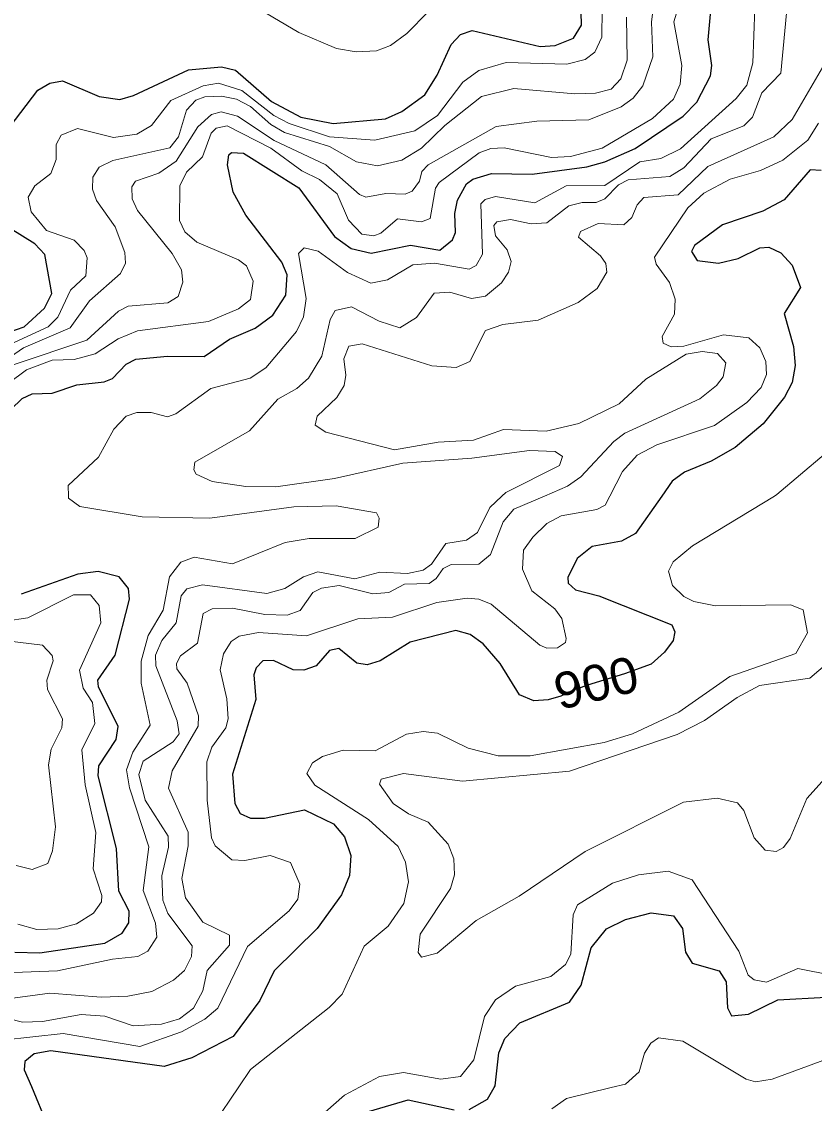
# Model space of a CAD drawing. Extents: x 473.9 to 500, y 7733.1 to 7760.8.
# Drawn here: x 484.023 to 485.784, y 7735.72 to 7738.123 of the extents above; entities that cross this region are included whole.
import ezdxf
from ezdxf.enums import TextEntityAlignment as Align

# ---------------------------------------------------------------- set-up
doc = ezdxf.new("R2010")
doc.units = 0
doc.header["$LTSCALE"] = 0.032
doc.layers.add('1', color=7, linetype='Continuous', lineweight=25)
doc.layers.add('2', color=7, linetype='Continuous', lineweight=13)
doc.layers.add('61', color=7, linetype='Continuous')

msp = doc.modelspace()

# ---------------------------------------------------------------- linework, layer by layer
at = {"layer": '1'}
for points in [[(484.9192, 7737.9607), (484.9465, 7738.0038), (484.977, 7738.0723), (484.9983, 7738.0943), (485.0241, 7738.103), (485.1747, 7738.0679), (485.2086, 7738.0698), (485.2494, 7738.086), (485.267, 7738.1149), (485.2622, 7738.2885)], [(485.5531, 7738.0026), (485.5561, 7738.0253), (485.5483, 7738.0828), (485.5549, 7738.156)], [(483.9336, 7737.8065), (484.0593, 7737.9707), (484.086, 7737.9864), (484.1142, 7737.9914), (484.1956, 7737.9567), (484.2415, 7737.9498), (484.272, 7737.9587), (484.3942, 7738.0157), (484.4673, 7738.0227), (484.498, 7738.0154), (484.5781, 7737.9452), (484.6435, 7737.9109), (484.7154, 7737.8966), (484.8316, 7737.9072), (484.8679, 7737.9232), (484.9192, 7737.9607)], [(483.9989, 7737.2616), (484.0248, 7737.2856), (484.0465, 7737.2963), (484.091, 7737.2979), (484.1456, 7737.3163), (484.2067, 7737.323), (484.2248, 7737.3306), (484.2555, 7737.3618), (484.2772, 7737.3734), (484.3473, 7737.3803), (484.429, 7737.3789), (484.4848, 7737.4178), (484.5421, 7737.4419), (484.581, 7737.4713), (484.6101, 7737.5151), (484.6129, 7737.5605), (484.6011, 7737.5886), (484.5216, 7737.6932), (484.4928, 7737.7442), (484.4806, 7737.8052), (484.4836, 7737.8274), (484.4893, 7737.8321), (484.516, 7737.8306), (484.6391, 7737.7538), (484.7184, 7737.646), (484.755, 7737.6187), (484.7994, 7737.6088), (484.887, 7737.6263), (484.9519, 7737.6152), (484.9806, 7737.6382), (484.9871, 7737.6543), (484.9855, 7737.6971), (484.9912, 7737.7265), (485.0116, 7737.7625), (485.0257, 7737.7727), (485.0668, 7737.7855), (485.1575, 7737.7841), (485.2784, 7737.8007), (485.319, 7737.8118), (485.3859, 7737.8413), (485.4924, 7737.913), (485.5233, 7737.9441), (485.5531, 7738.0026)], [(485.7991, 7737.792), (485.7746, 7737.7937), (485.7168, 7737.7274), (485.6694, 7737.7023), (485.5804, 7737.6714), (485.5181, 7737.6254), (485.5113, 7737.6126), (485.524, 7737.5925), (485.5714, 7737.5863), (485.6149, 7737.5967), (485.6628, 7737.6203), (485.6831, 7737.622), (485.7095, 7737.6098), (485.7347, 7737.5822), (485.7532, 7737.5328), (485.7173, 7737.4747), (485.738, 7737.4015), (485.7413, 7737.3595)], [(483.9092, 7737.4033), (484.0291, 7737.445), (484.0737, 7737.4866), (484.0902, 7737.5189), (484.0747, 7737.6057), (484.0524, 7737.6296), (483.9482, 7737.6939)], [(485.7413, 7737.3595), (485.7347, 7737.3218), (485.7175, 7737.289), (485.6701, 7737.2297), (485.6085, 7737.177), (485.5549, 7737.1465), (485.4953, 7737.1223), (485.4679, 7737.1022), (485.445, 7737.0693), (485.3868, 7736.9858), (485.3559, 7736.969), (485.2902, 7736.9569), (485.2572, 7736.9302), (485.2365, 7736.8881), (485.2375, 7736.8758), (485.2535, 7736.8606), (485.3054, 7736.8473), (485.4672, 7736.7833), (485.4742, 7736.7677), (485.4701, 7736.7486), (485.4513, 7736.7222), (485.4216, 7736.6959), (485.3623, 7736.6742), (485.29, 7736.6524), (485.2481, 7736.6381), (485.2207, 7736.6247), (485.193, 7736.6166), (485.161, 7736.6141), (485.1288, 7736.6277), (485.0863, 7736.6973), (485.0486, 7736.7407), (485.0194, 7736.7615), (484.9876, 7736.7708), (484.8863, 7736.7446), (484.8193, 7736.7032), (484.7911, 7736.6943), (484.7677, 7736.6979), (484.7275, 7736.7307), (484.7073, 7736.7265), (484.6774, 7736.6923), (484.65, 7736.6823), (484.6266, 7736.683), (484.583, 7736.7039), (484.5588, 7736.703), (484.5444, 7736.6876), (484.5391, 7736.6719), (484.5432, 7736.6171), (484.4913, 7736.4514), (484.497, 7736.3862), (484.5083, 7736.364), (484.5319, 7736.3537), (484.5625, 7736.3537), (484.6519, 7736.3721), (484.7158, 7736.3412), (484.7406, 7736.3127), (484.7545, 7736.2706), (484.7514, 7736.2266), (484.7337, 7736.1832), (484.68, 7736.1091), (484.5842, 7736.0149), (484.552, 7735.9489), (484.4932, 7735.8689), (484.4011, 7735.8212), (484.34, 7735.8022), (484.0878, 7735.8374), (484.0509, 7735.8306), (484.03, 7735.8137), (484.029, 7735.795), (484.0448, 7735.7575), (484.0801, 7735.6735)], [(484.008, 7736.0563), (484.0637, 7736.0547), (484.2081, 7736.0761), (484.2467, 7736.0982), (484.2617, 7736.1215), (484.2618, 7736.1472), (484.239, 7736.1914), (484.2343, 7736.2867), (484.1935, 7736.4476), (484.1946, 7736.4702), (484.2333, 7736.5283), (484.2376, 7736.5573), (484.1938, 7736.6453), (484.1927, 7736.6601), (484.2312, 7736.7155), (484.263, 7736.8405), (484.2605, 7736.8642), (484.24, 7736.8898), (484.1932, 7736.9019), (484.1482, 7736.8957), (484.0222, 7736.8514)], [(485.0172, 7735.7065), (485.0579, 7735.73), (485.0729, 7735.7559), (485.0751, 7735.7597), (485.0829, 7735.8325), (485.0964, 7735.8648), (485.1299, 7735.8994), (485.2399, 7735.9449), (485.2662, 7735.9828), (485.2881, 7736.0661), (485.3222, 7736.1079), (485.3645, 7736.1291), (485.4213, 7736.1438), (485.471, 7736.1372)], [(485.471, 7736.1372), (485.4914, 7736.1087), (485.4977, 7736.0564), (485.5127, 7736.0317), (485.573, 7736.0144), (485.5885, 7735.9905), (485.5913, 7735.9328), (485.6, 7735.9147), (485.638, 7735.9182), (485.703, 7735.9505), (485.81, 7735.9561)], [(484.7815, 7735.6983), (484.8822, 7735.7282), (484.9839, 7735.7057)]]:
    msp.add_lwpolyline(points, dxfattribs=at)
at = {"layer": '2'}
for points in [[(485.0358, 7736.9886), (485.063, 7737.044), (485.0901, 7737.0693), (485.0988, 7737.0774), (485.2177, 7737.1369), (485.2248, 7737.1568), (485.2084, 7737.1681), (485.151, 7737.1704), (485.0229, 7737.1535), (484.8697, 7737.1424), (484.7184, 7737.1083), (484.5876, 7737.0894), (484.5213, 7737.0902), (484.4467, 7737.1015), (484.4111, 7737.1177), (484.4058, 7737.1273), (484.4083, 7737.1444), (484.5291, 7737.2144), (484.5925, 7737.2846), (484.6346, 7737.3082), (484.6602, 7737.3309), (484.6903, 7737.3797), (484.7084, 7737.4611), (484.72, 7737.4817), (484.7556, 7737.4895), (484.8173, 7737.4574), (484.8633, 7737.4432), (484.9002, 7737.4656), (484.9394, 7737.5196), (484.9741, 7737.5219), (485.0224, 7737.5083), (485.0535, 7737.5134), (485.089, 7737.5431), (485.1045, 7737.5662), (485.1105, 7737.5902), (485.1021, 7737.6159), (485.0756, 7737.6469), (485.0723, 7737.6698), (485.0786, 7737.678), (485.1092, 7737.6836), (485.1554, 7737.674), (485.1902, 7737.676), (485.2385, 7737.7135), (485.2685, 7737.7213), (485.2991, 7737.721), (485.3189, 7737.7296), (485.3489, 7737.7603), (485.3708, 7737.7719), (485.463, 7737.7793), (485.4943, 7737.7985), (485.5552, 7737.863), (485.6271, 7737.8915), (485.6468, 7737.9104), (485.6674, 7737.9646), (485.7095, 7738.0083), (485.7274, 7738.1971)], [(484.9268, 7738.1455), (484.879, 7738.0965), (484.8425, 7738.0697), (484.8118, 7738.0578), (484.7663, 7738.0557), (484.7228, 7738.0633), (484.6391, 7738.0988), (484.4493, 7738.2114)], [(484.8214, 7737.6532), (484.8583, 7737.6847), (484.9114, 7737.678), (484.9308, 7737.6857), (484.9424, 7737.7528), (484.9509, 7737.7654), (485.0398, 7737.8315), (485.0653, 7737.8409), (485.0954, 7737.8427), (485.1999, 7737.8211), (485.2426, 7737.8231), (485.313, 7737.8417), (485.4245, 7737.9078), (485.4711, 7737.9511), (485.4863, 7737.9843), (485.4896, 7738.0255), (485.4719, 7738.1228), (485.4904, 7738.1831)], [(483.9509, 7737.385), (484.0823, 7737.4451), (484.1034, 7737.4667), (484.1319, 7737.5264), (484.166, 7737.5586), (484.1685, 7737.5983), (484.1624, 7737.6149), (484.1402, 7737.6376), (484.0783, 7737.6587), (484.0443, 7737.7008), (484.0375, 7737.7331), (484.0524, 7737.7585), (484.088, 7737.7857), (484.0998, 7737.817), (484.1, 7737.8497), (484.1112, 7737.8706), (484.1471, 7737.8854), (484.2276, 7737.8659), (484.2794, 7737.8728), (484.3114, 7737.8919), (484.3544, 7737.9478), (484.4263, 7737.9804), (484.4607, 7737.9859), (484.5121, 7737.97), (484.5831, 7737.9146), (484.6178, 7737.897), (484.7073, 7737.867), (484.808, 7737.8597), (484.8969, 7737.8807), (484.9471, 7737.9147), (485.003, 7737.9888), (485.0385, 7738.0146), (485.0996, 7738.0323), (485.2341, 7738.0282), (485.2752, 7738.0392), (485.2961, 7738.0551), (485.3117, 7738.0882), (485.3129, 7738.1509)], [(485.4284, 7738.1717), (485.4221, 7738.1215), (485.4252, 7738.045), (485.403, 7737.98), (485.3813, 7737.9532), (485.3551, 7737.9335), (485.2829, 7737.9047), (485.1677, 7737.9022), (485.0772, 7737.8901), (484.926, 7737.8048), (484.912, 7737.7904), (484.9073, 7737.7684), (484.8909, 7737.7466), (484.8753, 7737.7399), (484.832, 7737.7414), (484.788, 7737.7334), (484.7736, 7737.7387), (484.6989, 7737.8048), (484.5845, 7737.8592), (484.5028, 7737.9128), (484.4661, 7737.9223), (484.4452, 7737.9166), (484.4143, 7737.8896), (484.3668, 7737.8129), (484.3277, 7737.7865), (484.2764, 7737.7687), (484.2678, 7737.756), (484.269, 7737.7292), (484.2809, 7737.7034), (484.3579, 7737.6078), (484.3781, 7737.5715), (484.3815, 7737.5446), (484.3711, 7737.5124), (484.3481, 7737.4985), (484.2597, 7737.491), (484.2386, 7737.4796), (484.1683, 7737.4156), (484.0067, 7737.3614)], [(485.6518, 7738.1525), (485.6472, 7738.0314), (485.6339, 7737.9821), (485.6101, 7737.9521), (485.4864, 7737.8402), (485.4432, 7737.8187), (485.3966, 7737.8118), (485.3186, 7737.7588), (485.2331, 7737.7583), (485.1629, 7737.7207), (485.0761, 7737.7349), (485.0528, 7737.7277), (485.0435, 7737.7182), (485.0473, 7737.6066), (485.0329, 7737.5815), (485.0175, 7737.5734), (484.9404, 7737.5862), (484.8922, 7737.583), (484.8362, 7737.5492), (484.7991, 7737.5421)], [(483.8919, 7737.3051), (484.0273, 7737.3981), (484.1311, 7737.4428), (484.1739, 7737.5031), (484.2431, 7737.5632), (484.2536, 7737.5865), (484.2527, 7737.6101), (484.2307, 7737.667), (484.1893, 7737.726), (484.1808, 7737.7505), (484.1816, 7737.7773), (484.1953, 7737.7994), (484.2258, 7737.8148), (484.3524, 7737.8423), (484.3717, 7737.8672), (484.3893, 7737.9265), (484.4102, 7737.9482), (484.43, 7737.9562), (484.4671, 7737.9577), (484.5003, 7737.951), (484.5319, 7737.9343), (484.5767, 7737.8946), (484.6073, 7737.8765), (484.707, 7737.8458), (484.7669, 7737.8118), (484.8139, 7737.8025), (484.8676, 7737.8154), (484.9117, 7737.8416), (484.963, 7737.8925), (485.0445, 7737.9567), (485.1164, 7737.9745), (485.2517, 7737.9626), (485.2981, 7737.9642), (485.333, 7737.973), (485.3539, 7737.996), (485.3681, 7738.0373), (485.3666, 7738.1328)], [(485.8024, 7738.0211), (485.7351, 7737.9059), (485.694, 7737.8674), (485.5476, 7737.8014), (485.4814, 7737.7379), (485.4051, 7737.7326), (485.3904, 7737.7159), (485.379, 7737.6879), (485.361, 7737.6717), (485.304, 7737.6746), (485.2648, 7737.6571), (485.2604, 7737.6443), (485.3092, 7737.6031), (485.3207, 7737.5854), (485.3232, 7737.5664), (485.3014, 7737.53), (485.2598, 7737.4993), (485.1709, 7737.4602), (485.092, 7737.4501), (485.0534, 7737.4366), (485.0191, 7737.3678), (484.9881, 7737.3547), (484.9346, 7737.3582), (484.7795, 7737.4076), (484.7501, 7737.402), (484.7387, 7737.3743), (484.7433, 7737.338), (484.7395, 7737.3146), (484.7233, 7737.288), (484.6794, 7737.2467), (484.6754, 7737.227), (484.6993, 7737.2108), (484.8516, 7737.1717), (484.9485, 7737.189), (485.0273, 7737.1934), (485.0937, 7737.2172), (485.188, 7737.2132), (485.261, 7737.2303), (485.3504, 7737.2743), (485.4099, 7737.3289), (485.4995, 7737.3842), (485.5348, 7737.3901), (485.5692, 7737.3858), (485.5875, 7737.365), (485.5817, 7737.334), (485.5668, 7737.3145), (485.5299, 7737.2854), (485.3634, 7737.2091), (485.3385, 7737.1906), (485.2653, 7737.1119)], [(483.9805, 7735.8609), (484.1156, 7735.8754), (484.286, 7735.8464), (484.3785, 7735.8794), (484.4299, 7735.9075), (484.4589, 7735.9316), (484.5248, 7736.0691), (484.6173, 7736.1479), (484.6366, 7736.1737), (484.6414, 7736.2074), (484.6205, 7736.2557), (484.5755, 7736.2709), (484.5192, 7736.2597), (484.4902, 7736.2613), (484.4532, 7736.2926), (484.4452, 7736.3103), (484.4355, 7736.394), (484.4347, 7736.4792), (484.446, 7736.5113), (484.4766, 7736.5548), (484.4822, 7736.5741), (484.479, 7736.6191), (484.4645, 7736.6834), (484.4717, 7736.7188), (484.4886, 7736.7461), (484.5063, 7736.7582), (484.5497, 7736.7662), (484.6559, 7736.759), (484.77, 7736.7968), (484.8472, 7736.8), (484.9453, 7736.8329), (485.0128, 7736.8426), (485.0386, 7736.8402), (485.0659, 7736.8289), (485.1744, 7736.7381), (485.1897, 7736.7316), (485.2138, 7736.7324), (485.2315, 7736.7437), (485.2331, 7736.7525), (485.2235, 7736.7976), (485.2074, 7736.8185), (485.1567, 7736.8587), (485.1358, 7736.9069), (485.1383, 7736.9487), (485.1584, 7736.9777), (485.1897, 7737.0082), (485.2219, 7737.0251), (485.3007, 7737.0396), (485.3192, 7737.0492), (485.3296, 7737.0693), (485.3578, 7737.124), (485.3907, 7737.1602), (485.4341, 7737.1827), (485.562, 7737.2261), (485.6343, 7737.2768), (485.6657, 7737.3105), (485.6778, 7737.3395), (485.6761, 7737.3684), (485.6633, 7737.3982), (485.6384, 7737.4207), (485.5821, 7737.4271), (485.4944, 7737.4022), (485.4663, 7737.4006), (485.4486, 7737.4086), (485.4462, 7737.4239), (485.4735, 7737.4729), (485.4751, 7737.5067), (485.4623, 7737.5437), (485.4325, 7737.5839), (485.4293, 7737.6), (485.5033, 7737.7093), (485.5387, 7737.7423), (485.5974, 7737.7728), (485.6641, 7737.7921), (485.7139, 7737.8154), (485.7694, 7737.8597), (485.7935, 7737.8975)], [(483.9933, 7737.3194), (484.0342, 7737.3498), (484.0914, 7737.3707), (484.1396, 7737.3724), (484.1868, 7737.3849), (484.2376, 7737.4182), (484.2806, 7737.4365), (484.4382, 7737.4569), (484.5046, 7737.485), (484.5318, 7737.506), (484.5377, 7737.5463), (484.5224, 7737.5808), (484.5053, 7737.5942), (484.4122, 7737.6329), (484.386, 7737.6558), (484.3742, 7737.6809), (484.3743, 7737.7584), (484.3898, 7737.7885), (484.425, 7737.8227), (484.4439, 7737.8754), (484.4551, 7737.886), (484.48, 7737.8917), (484.5771, 7737.8422), (484.646, 7737.7919), (484.6852, 7737.7723), (484.7238, 7737.7406), (484.749, 7737.6818), (484.779, 7737.6509), (484.8055, 7737.6473), (484.8214, 7737.6532)], [(484.7991, 7737.5421), (484.7469, 7737.5655), (484.6821, 7737.6132), (484.6511, 7737.6202), (484.6381, 7737.6078), (484.6556, 7737.5082), (484.6495, 7737.467), (484.6336, 7737.4348), (484.5657, 7737.3538), (484.5308, 7737.3308), (484.4434, 7737.308), (484.3661, 7737.2515), (484.3474, 7737.2455), (484.3111, 7737.2549), (484.2795, 7737.2549), (484.2555, 7737.2469), (484.2281, 7737.2175), (484.1938, 7737.1557), (484.1266, 7737.0927), (484.1274, 7737.0693), (484.1276, 7737.0644), (484.1524, 7737.0462), (484.2913, 7737.023), (484.4414, 7737.0203), (484.6279, 7737.045), (484.7217, 7737.0476), (484.8112, 7737.0319), (484.8175, 7737.02), (484.8152, 7737.0004), (484.7641, 7736.9749), (484.6617, 7736.9751), (484.6086, 7736.9661), (484.4918, 7736.919), (484.4062, 7736.9333), (484.3767, 7736.9226), (484.3516, 7736.8901), (484.3379, 7736.8155), (484.3042, 7736.7597), (484.2884, 7736.7028), (484.2885, 7736.6539), (484.309, 7736.5603), (484.2701, 7736.5006), (484.2562, 7736.4609), (484.2625, 7736.4213), (484.3061, 7736.2904), (484.2932, 7736.1935), (484.3205, 7736.1205), (484.3238, 7736.0894), (484.3033, 7736.0582), (484.2811, 7736.0467), (484.2248, 7736.0409), (484.1032, 7736.0151), (483.9863, 7736.0102)], [(485.8062, 7737.1619), (485.701, 7737.0725), (485.6957, 7737.0693), (485.5133, 7736.9587), (485.4708, 7736.9229), (485.4599, 7736.9024), (485.4688, 7736.8706), (485.4943, 7736.8461), (485.5167, 7736.8351), (485.5648, 7736.8257), (485.7309, 7736.828), (485.7591, 7736.8169), (485.7686, 7736.7657), (485.7427, 7736.7196), (485.5966, 7736.6688), (485.4834, 7736.589), (485.3799, 7736.5409), (485.3173, 7736.5219), (485.153, 7736.4926), (485.0819, 7736.492), (485.0149, 7736.5094), (484.9468, 7736.5426), (484.9149, 7736.546), (484.8782, 7736.5405), (484.8082, 7736.5036), (484.7371, 7736.5051), (484.6917, 7736.4906), (484.669, 7736.4765), (484.6568, 7736.4531), (484.6748, 7736.4273), (484.794, 7736.3509), (484.8597, 7736.2907), (484.8758, 7736.2562), (484.8824, 7736.2127), (484.872, 7736.164), (484.8377, 7736.1136), (484.7844, 7736.0698), (484.7349, 7735.9633), (484.7061, 7735.9335), (484.5316, 7735.7954), (484.5056, 7735.7568), (484.449, 7735.6725)], [(485.2653, 7737.1119), (485.2359, 7737.0913), (485.1845, 7737.0693), (485.1167, 7737.0402), (485.0927, 7737.0119), (485.0645, 7736.9395), (485.0388, 7736.9178), (484.9775, 7736.9173), (484.9596, 7736.9086), (484.9443, 7736.8859), (484.9285, 7736.8751), (484.8737, 7736.8738), (484.8386, 7736.8551), (484.8032, 7736.8523), (484.7283, 7736.8705), (484.689, 7736.8645), (484.6704, 7736.855), (484.6423, 7736.8151), (484.6129, 7736.8049), (484.5637, 7736.8062), (484.492, 7736.8201), (484.4467, 7736.8191), (484.4265, 7736.8086), (484.4141, 7736.7423), (484.3765, 7736.7142), (484.3672, 7736.6972), (484.3678, 7736.6853), (484.3906, 7736.6538), (484.4164, 7736.5809), (484.4153, 7736.558), (484.3578, 7736.4588), (484.3495, 7736.4203), (484.3929, 7736.3226), (484.393, 7736.2925), (484.3793, 7736.2197), (484.3874, 7736.1771), (484.4258, 7736.1232), (484.4847, 7736.0943), (484.4848, 7736.0715), (484.4352, 7736.0155), (484.4257, 7735.9702), (484.405, 7735.9322), (484.3741, 7735.9085), (484.3337, 7735.8961), (484.2709, 7735.8928), (484.2083, 7735.9139), (484.1557, 7735.9179), (484.0694, 7735.9019), (484.0254, 7735.9011), (483.897, 7735.9332)], [(483.9928, 7735.9526), (484.086, 7735.9654), (484.1996, 7735.9566), (484.2589, 7735.9585), (484.3126, 7735.9691), (484.3603, 7735.9939), (484.3848, 7736.0153), (484.4008, 7736.0464), (484.4022, 7736.0706), (484.3482, 7736.1418), (484.3367, 7736.172), (484.335, 7736.2261), (484.3494, 7736.2893), (484.3486, 7736.3135), (484.2974, 7736.3935), (484.2836, 7736.4507), (484.2934, 7736.4806), (484.3595, 7736.5233), (484.3731, 7736.5414), (484.3689, 7736.5702), (484.3215, 7736.6918), (484.3206, 7736.7155), (484.3348, 7736.7485), (484.3668, 7736.7878), (484.3777, 7736.8474), (484.39, 7736.8632), (484.4253, 7736.8723), (484.5679, 7736.8528), (484.6081, 7736.8637), (484.6494, 7736.8898), (484.6815, 7736.9012), (484.763, 7736.8852), (484.8188, 7736.9005), (484.8804, 7736.8973), (484.915, 7736.905), (484.9338, 7736.918), (484.9653, 7736.9636), (485.0117, 7736.9711), (485.0358, 7736.9886)], [(484.0148, 7736.1186), (484.0571, 7736.1067), (484.1042, 7736.1077), (484.1454, 7736.1194), (484.1826, 7736.1427), (484.2003, 7736.1678), (484.2015, 7736.1821), (484.1823, 7736.2411), (484.1878, 7736.3221), (484.1645, 7736.4282), (484.1567, 7736.5053), (484.1862, 7736.5638), (484.1806, 7736.6109), (484.1602, 7736.6427), (484.1517, 7736.6828), (484.1989, 7736.7873), (484.1958, 7736.8264), (484.1761, 7736.8499), (484.1384, 7736.8501), (484.0373, 7736.7988), (483.9871, 7736.791)], [(483.9653, 7736.751), (484.0698, 7736.7383), (484.0914, 7736.715), (484.0936, 7736.7035), (484.0794, 7736.6602), (484.0805, 7736.6393), (484.1139, 7736.5744), (484.1123, 7736.5548), (484.0886, 7736.5068), (484.0828, 7736.4722), (484.0987, 7736.3348), (484.0921, 7736.2813), (484.0817, 7736.2528), (484.047, 7736.2396), (484.0112, 7736.2484)], [(485.6751, 7736.2825), (485.6503, 7736.3104), (485.6272, 7736.3708), (485.613, 7736.3876), (485.5684, 7736.398), (485.4931, 7736.3896), (485.275, 7736.2796), (485.1285, 7736.1803), (485.0332, 7736.1266), (484.9463, 7736.0538), (484.9111, 7736.0452), (484.9043, 7736.0553), (484.9083, 7736.096), (484.9757, 7736.1978), (484.9846, 7736.2282), (484.9835, 7736.2632), (484.9706, 7736.2964), (484.9266, 7736.3448), (484.8826, 7736.3636), (484.8488, 7736.3864), (484.8185, 7736.4293), (484.8218, 7736.4405), (484.8711, 7736.4532), (485.0026, 7736.4357), (485.2405, 7736.4585), (485.4796, 7736.5397), (485.5402, 7736.5708), (485.6125, 7736.6222), (485.6619, 7736.6484), (485.7741, 7736.665), (485.8139, 7736.6991)], [(485.8016, 7736.435), (485.7675, 7736.3973), (485.7301, 7736.3085), (485.7158, 7736.2889), (485.6996, 7736.2795), (485.6751, 7736.2825)], [(484.6423, 7735.6517), (484.7405, 7735.7385), (484.7736, 7735.7564), (484.8182, 7735.7804), (484.8711, 7735.7893), (484.9544, 7735.774), (484.998, 7735.78), (485.0275, 7735.8171), (485.0515, 7735.913), (485.0756, 7735.95), (485.1201, 7735.9805), (485.1988, 7736.0021), (485.2314, 7736.0289), (485.2428, 7736.0519), (485.2483, 7736.1392), (485.2581, 7736.1616), (485.3355, 7736.2095), (485.3934, 7736.2277), (485.4592, 7736.2364), (485.513, 7736.217), (485.6163, 7736.0583), (485.6372, 7736.0049), (485.6502, 7735.9949), (485.6777, 7735.9897), (485.7477, 7736.02), (485.8258, 7736.0041)], [(485.8473, 7735.8318), (485.6903, 7735.7738), (485.6534, 7735.7685), (485.6327, 7735.7738), (485.4917, 7735.8586), (485.438, 7735.8656), (485.4207, 7735.8539), (485.4069, 7735.8321), (485.3949, 7735.7904), (485.3647, 7735.7633), (485.3325, 7735.7555), (485.2334, 7735.7314), (485.2012, 7735.7081)]]:
    msp.add_lwpolyline(points, dxfattribs=at)

# ---------------------------------------------------------------- texts
at = {"layer": '61', "width": 1.05}
msp.add_text('900', height=0.08, rotation=13.536, dxfattribs=at).set_placement((485.3087, 7736.6158), align=Align.CENTER)

doc.saveas('drawing.dxf')
